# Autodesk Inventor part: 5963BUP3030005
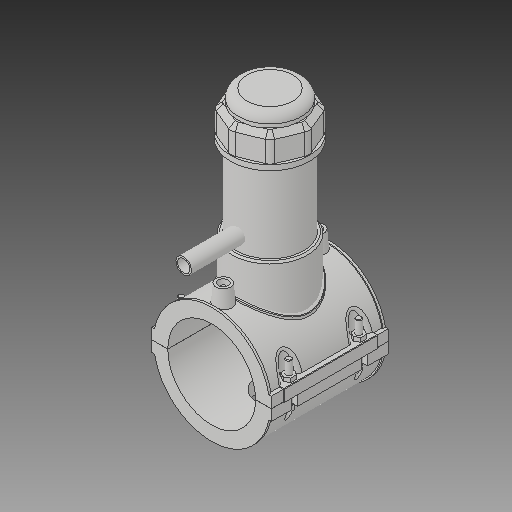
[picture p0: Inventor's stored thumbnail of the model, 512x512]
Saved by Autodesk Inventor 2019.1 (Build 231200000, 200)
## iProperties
Created: 2017-07
Part Number: 5963BUP3030005
Material: Generic
Description: PLASSON TAPPING SADDLE 3''IPS x 1/2''CTS
Document SubType Name: Modeling
Designer: KIM
Density: 1 g/cm^3
Appearance: Default
Author: KIM
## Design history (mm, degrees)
derived "5963BBP_5963BUP.ipt"
feature "Solid1::5963BBP_5963BUP.ipt"
feature "Solid2::5963BBP_5963BUP.ipt"
feature "Solid3::5963BBP_5963BUP.ipt"
tag "TaggingFeature1"
body "Solid1"
body "Solid2"
body "Solid3"
other parameters: "d0" = 88.7, "d2" = 120.904, "d3" = 22.175, "d4" = 118.11, "d5" = 0, "d6" = 0.1, "d8" = 0, "d19" = 6, "d20" = 6, "d21" = 70.866, "d23" = 0, "d24" = 35.433, "d26" = 0, "d27" = 3, "d28" = 3, "d29" = 3, "d30" = 29.56667, "d31" = 6, "d32" = 0, "d33" = 0, "d34" = 0.6, "d40" = 59.9612, "d41" = 79.83, "d43" = 0, "d45" = 0, "d47" = 128.521, "d70" = 15, "d72" = 0, "d73" = 6, "d75" = 5, "d76" = 0, "d77" = 4.435, "d78" = 74.35, "d79" = 15, "d80" = 47.244, "d82" = 5 deg, "d84" = 4, "d85" = 14, "d86" = 0, "d87" = 3, "d88" = 0, "d89" = 1, "d90" = 1, "d91" = 94.488, "d92" = 0, "d93" = 0.5, "d94" = 46.68421, "d96" = 117.6162, "d97" = 2.3622, "d98" = 0, "d102" = 0.887, "d120" = 140 deg, "d121" = 24.228, "d122" = 20 deg, "d123" = 230.62, "d124" = 69.186, "d126" = 0, "d143" = 91.361, "d145" = 20.46923, "d149" = 1.3305, "d150" = 22.51615, "d153" = 118.11, "d154" = 0, "d156" = 57.655, "d157" = 160 deg, "d159" = 5.322, "d161" = 1.3305, "d162" = 70.866, "d163" = 0, "d164" = 44.35, "d167" = 8.87, "d168" = 56.24878, "d170" = 3.2805, "d172" = 0, "d173" = 1, "d175" = 44.35, "d176" = 20 deg, "d177" = 6.209, "d178" = 26.61, "d180" = 0, "d183" = 10.644, "d184" = 4.9672, "d185" = 38.38575, "d186" = 38.38575, "d187" = 57.655, "d188" = 7.983, "d189" = 6.209, "d190" = 0, "d191" = 86.4825, "d193" = 6.9984, "d194" = 4.13385, "d195" = 90 deg, "d197" = 0, "d199" = 0, "d200" = 13.305, "d202" = 0, "d203" = 177.038, "d204" = 75.8385, "d205" = 55.881, "d206" = 67.8555, "d207" = 132.7785, "d208" = 138.08964, "d209" = 164.64534, "d210" = 68.6538, "d211" = 79.83, "d212" = 63.864, "d213" = 51.4116, "d216" = 0, "d217" = 8.87, "d218" = 8.87, "d219" = 1.774, "d222" = 88.7, "d224" = 0, "d225" = 65.024, "d226" = 15.8, "d227" = 12.64, "d228" = 87.376, "d230" = 5.322, "d_" = 88.7, "B_" = 120.904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
